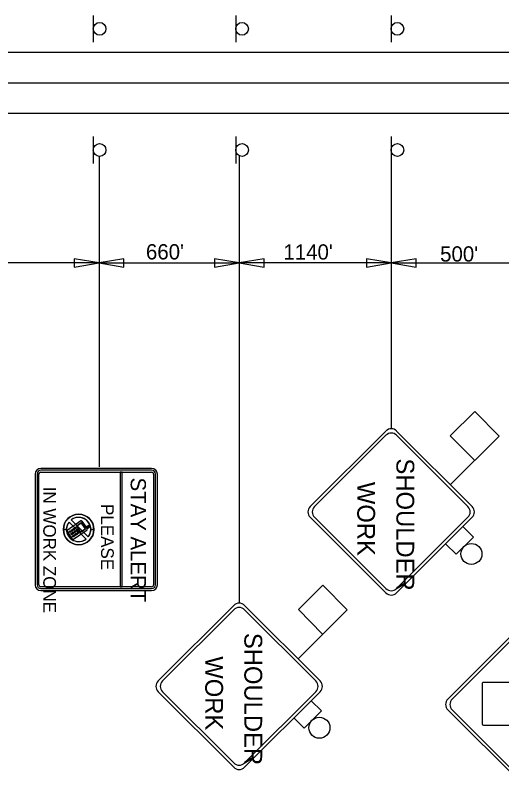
# Model space of a CAD drawing. Extents: x 2155255 to 2162649, y 140388 to 141878.
# Drawn here: x 2156772.7 to 2156963.6, y 140653 to 140956.6 of the extents above; entities that cross this region are included whole.
import ezdxf

# ---------------------------------------------------------------- set-up
doc = ezdxf.new("R2010")
doc.units = 0
for name, color, linetype in [('5', 7, 'Continuous'), ('Default', 7, 'Continuous'), ('PR_Dimensions1', 7, 'Continuous'), ('PR_Traffic_Control_Devices_Temp', 7, 'Continuous'), ('PR_Traffic_Temp_Txt', 7, 'Continuous'), ('TOPO_Asphalt', 7, 'Continuous')]:
    doc.layers.add(name, color=color, linetype=linetype)

# ---------------------------------------------------------------- blocks, each defined once
blk = doc.blocks.new('FLSHFLAG')
at = {"layer": 'Default'}
for p, q in [((-1.202, 14.125), (0.838, 16.147)), ((0.838, 16.147), (4.9, 12.085)), ((0.819, 12.085), (-1.202, 14.125)), ((0.819, 12.085), (2.86, 14.106)), ((9.258, 14.004), (8.403, 13.149)), ((9.258, 14.004), (10.685, 12.576)), ((10.685, 12.576), (9.831, 11.722))]:
    blk.add_line(p, q, dxfattribs=at)
blk.add_circle((10.653, 13.836), 0.873, dxfattribs=at)
blk = doc.blocks.new('TCSIGN')
at = {"layer": 'Default'}
blk.add_line((5.26, 2.5), (-5.26, 2.5), dxfattribs=at)
blk.add_circle((0, 0), 2.5, dxfattribs=at)
blk = doc.blocks.new('Arrowhd')
at = {"layer": 'Default'}
blk.add_lwpolyline([(0.3175, -0.0529), (0.3175, 0.0529), (0, 0)], close=True, dxfattribs=at)
blk = doc.blocks.new('W3-5_1')
at = {"layer": '5'}
for p, q in [((0.808, 7.633), (6.735, 13.56)), ((13.56, 7.633), (7.633, 13.56)), ((6.735, 0.808), (0.808, 6.735)), ((7.633, 0.808), (13.56, 6.735))]:
    blk.add_line(p, q, dxfattribs=at)
for centre, start, end in [((7.184, 13.111), 45, 135), ((1.257, 7.184), 135, 225), ((13.111, 7.184), 315, 45), ((7.184, 1.257), 225, 315)]:
    blk.add_arc(centre, 0.635, start, end, dxfattribs=at)
at = {"layer": 'Default'}
for p, q in [((0.448, 7.633), (6.735, 13.919)), ((13.919, 7.633), (7.633, 13.919)), ((6.95, 12.723), (4.277, 10.304)), ((9.984, 10.322), (7.366, 12.687)), ((5.352, 8.019), (5.352, 3.415)), ((8.797, 8.13), (5.464, 8.13)), ((8.908, 3.415), (8.908, 8.019)), ((6.735, 0.449), (0.448, 6.735)), ((7.633, 0.449), (13.919, 6.735)), ((5.464, 3.304), (8.797, 3.304))]:
    blk.add_line(p, q, dxfattribs=at)
for points in [[(4.277, 10.304), (6.95, 12.723)], [(7.366, 12.687), (9.984, 10.322)], [(4.584, 9.924), (6.553, 10.412), (6.553, 8.913), (7.745, 8.913), (7.745, 10.448), (9.677, 9.96)], [(9.677, 9.96), (7.745, 10.448), (7.745, 8.913), (6.553, 8.913), (6.553, 10.412), (4.584, 9.924)]]:
    blk.add_lwpolyline(points, dxfattribs=at)
for centre, radius, start, end in [((7.184, 13.47), 0.635, 45, 135), ((7.141, 12.512), 0.285, 37.91416, 132.14933), ((7.141, 12.512), 0.285, 37.91416, 132.14933), ((4.519, 10.186), 0.269, 154.09026, 283.9085), ((4.519, 10.186), 0.269, 154.09026, 283.9085), ((9.825, 10.146), 0.237, 231.34169, 47.91235), ((9.825, 10.146), 0.237, 231.34169, 47.91235), ((5.464, 8.019), 0.111, 90, 180), ((8.797, 8.019), 0.111, 0, 90), ((0.897, 7.184), 0.635, 135, 225), ((13.47, 7.184), 0.635, 315, 45), ((5.464, 3.415), 0.111, 180, 270), ((8.797, 3.415), 0.111, 270, 0), ((7.184, 0.898), 0.635, 225, 315)]:
    blk.add_arc(centre, radius, start, end, dxfattribs=at)
for s, p in [('SPEED', (5.649, 6.987)), ('LIMIT', (5.945, 5.929))]:
    blk.add_text(s, height=0.635, dxfattribs=at).set_placement(p)
blk = doc.blocks.new('CW21-5')
at = {"layer": '5'}
for p, q in [((0.318, 3.005), (2.651, 5.339)), ((5.338, 3.005), (3.005, 5.339)), ((2.651, 0.318), (0.318, 2.652)), ((3.005, 0.318), (5.338, 2.652))]:
    blk.add_line(p, q, dxfattribs=at)
for centre, start, end in [((2.828, 5.162), 45, 135), ((0.495, 2.828), 135, 225), ((5.162, 2.828), 315, 45), ((2.828, 0.495), 225, 315)]:
    blk.add_arc(centre, 0.25, start, end, dxfattribs=at)
at = {"layer": 'Default'}
for p, q in [((0.177, 3.005), (2.651, 5.48)), ((5.48, 3.005), (3.005, 5.48)), ((2.651, 0.177), (0.177, 2.652)), ((3.005, 0.177), (5.48, 2.652))]:
    blk.add_line(p, q, dxfattribs=at)
for centre, start, end in [((2.828, 5.303), 45, 135), ((0.353, 2.828), 135, 225), ((5.303, 2.828), 315, 45), ((2.828, 0.354), 225, 315)]:
    blk.add_arc(centre, 0.25, start, end, dxfattribs=at)
for s, p in [('SHOULDER', (1.076, 2.998)), ('WORK', (1.843, 1.717))]:
    blk.add_text(s, height=0.5833, dxfattribs=at).set_placement(p)

msp = doc.modelspace()

# ---------------------------------------------------------------- linework, layer by layer
at = {"layer": 'PR_Dimensions1'}
for p, q in [((2156805.54, 140901.15), (2156805.54, 140779.14)), ((2156860.58, 140901.56), (2156860.58, 140725.33)), ((2156920.31, 140901.63), (2156920.31, 140793.92)), ((2156805.54, 140859.25), (2156726.71, 140859.25)), ((2156805.54, 140859.25), (2156860.58, 140859.25)), ((2156920.31, 140859.25), (2156860.58, 140859.25)), ((2156920.31, 140859.25), (2156974.31, 140859.25))]:
    msp.add_line(p, q, dxfattribs=at)
at = {"layer": 'PR_Traffic_Control_Devices_Temp'}
for p, q in [((2156798.38, 140757.81), (2156793.01, 140754.05)), ((2156798.38, 140757.81), (2156793.01, 140754.05)), ((2156796.65, 140755.76), (2156798.55, 140757.09)), ((2156798.28, 140753.42), (2156796.65, 140755.76)), ((2156798.55, 140757.09), (2156800.18, 140754.75)), ((2156800.47, 140755.32), (2156798.81, 140757.69)), ((2156800.47, 140755.32), (2156798.81, 140757.69)), ((2156801.53, 140756.06), (2156800.47, 140755.32)), ((2156800.83, 140754.79), (2156800.47, 140755.32)), ((2156800.83, 140754.79), (2156800.47, 140755.32)), ((2156800.47, 140755.32), (2156800.83, 140754.79)), ((2156800.84, 140754.79), (2156801.9, 140755.53)), ((2156801.92, 140755.87), (2156801.85, 140755.97)), ((2156792.98, 140753.61), (2156795.01, 140750.71)), ((2156792.98, 140753.61), (2156795.01, 140750.71)), ((2156795.44, 140750.59), (2156800.8, 140754.35)), ((2156795.44, 140750.59), (2156800.8, 140754.35)), ((2156800.18, 140754.75), (2156798.28, 140753.42)), ((2156800.83, 140754.79), (2156800.83, 140754.79)), ((2156800.83, 140754.79), (2156800.84, 140754.79))]:
    msp.add_line(p, q, dxfattribs=at)
for points in [[(2156826.19, 140778.47), (2156814.19, 140778.47), (2156782.68, 140778.47)], [(2156826.19, 140777.72), (2156782.68, 140777.72)], [(2156782.68, 140776.97), (2156826.19, 140776.97)], [(2156780.43, 140776.22), (2156780.43, 140732.71)], [(2156781.18, 140776.22), (2156781.18, 140732.71)], [(2156781.18, 140776.22), (2156781.93, 140776.22)], [(2156781.93, 140732.71), (2156781.93, 140776.22), (2156781.18, 140776.22)], [(2156826.94, 140776.22), (2156826.94, 140732.71)], [(2156827.69, 140732.71), (2156827.69, 140776.22)], [(2156828.44, 140732.71), (2156828.44, 140776.22)], [(2156794.6, 140758.25), (2156801.29, 140751.56)], [(2156794.61, 140758.25), (2156801.29, 140751.56)], [(2156793.73, 140757.38), (2156800.42, 140750.69)], [(2156800.42, 140750.69), (2156793.74, 140757.38)], [(2156796.65, 140755.76), (2156798.55, 140757.09), (2156800.18, 140754.75), (2156798.28, 140753.42), (2156796.65, 140755.76)], [(2156801.92, 140755.87), (2156801.85, 140755.97)], [(2156791.51, 140754.47), (2156792.75, 140754.47)], [(2156792.75, 140754.47), (2156791.51, 140754.47)], [(2156792.98, 140753.61), (2156795.01, 140750.71)], [(2156803.51, 140754.47), (2156802.28, 140754.47)], [(2156802.28, 140754.47), (2156803.51, 140754.47)], [(2156826.19, 140731.96), (2156782.68, 140731.96)], [(2156782.68, 140731.21), (2156826.19, 140731.21)], [(2156782.68, 140730.46), (2156814.19, 140730.46), (2156826.19, 140730.46)]]:
    msp.add_lwpolyline(points, dxfattribs=at)
for points in [[(2156814.56, 140776.97), (2156813.81, 140776.97), (2156813.81, 140731.96), (2156814.56, 140731.96)], [(2156814.56, 140776.97), (2156813.81, 140776.97), (2156813.81, 140731.96), (2156814.56, 140731.96)], [(2156796.65, 140755.76), (2156798.28, 140753.42), (2156800.18, 140754.75), (2156798.55, 140757.09)], [(2156800.47, 140755.32), (2156801.53, 140756.06), (2156800.47, 140755.32), (2156800.84, 140754.79), (2156801.9, 140755.53), (2156800.84, 140754.79), (2156800.83, 140754.79), (2156800.83, 140754.79), (2156798.81, 140757.69), (2156798.81, 140757.69)]]:
    msp.add_lwpolyline(points, close=True, dxfattribs=at)
msp.add_circle((2156797.51, 140754.47), 6, dxfattribs=at)
msp.add_circle((2156797.51, 140754.47), 6, dxfattribs=at)
for centre, radius, start, end in [((2156782.68, 140776.22), 2.25, 90, 180), ((2156782.68, 140776.22), 1.5, 90, 180), ((2156782.68, 140776.22), 0.75, 90, 180), ((2156826.19, 140776.22), 2.25, 360, 90), ((2156826.19, 140776.22), 1.5, 360, 90), ((2156826.19, 140776.22), 0.75, 360, 90), ((2156797.51, 140754.47), 6, 0.0031, 179.9938), ((2156797.51, 140754.47), 4.77, 0.004, 127.5856), ((2156797.51, 140754.47), 4.77, 322.4137, 127.5863), ((2156797.51, 140754.47), 4.77, 322.4137, 127.5863), ((2156797.51, 140754.47), 4.77, 142.4137, 307.5863), ((2156797.51, 140754.47), 4.77, 142.4137, 307.5863), ((2156797.51, 140754.47), 4.77, 142.4117, 179.9933), ((2156797.51, 140754.47), 6, 179.9992, 359.9992), ((2156797.51, 140754.47), 4.77, 179.9991, 307.5866), ((2156797.51, 140754.47), 4.77, 322.4162, 0.0037), ((2156782.68, 140732.71), 2.25, 180, 270), ((2156782.68, 140732.71), 1.5, 180, 270), ((2156782.68, 140732.71), 0.75, 180, 270), ((2156826.19, 140732.71), 2.25, 270, 360), ((2156826.19, 140732.71), 1.5, 270, 360), ((2156826.19, 140732.71), 0.75, 270, 360)]:
    msp.add_arc(centre, radius, start, end, dxfattribs=at)
for centre, major_axis in [((2156796.19, 140755.02), (0.196, -0.28)), ((2156796.19, 140755.02), (0.196, -0.28)), ((2156796.19, 140755.02), (0.196, -0.28)), ((2156794.12, 140753.57), (0.196, -0.28)), ((2156794.12, 140753.57), (0.196, -0.28)), ((2156794.12, 140753.57), (0.196, -0.28)), ((2156794.74, 140752.68), (0.196, -0.28)), ((2156794.74, 140752.68), (0.196, -0.28)), ((2156794.74, 140752.68), (0.196, -0.28)), ((2156794.82, 140754.06), (0.196, -0.28)), ((2156794.82, 140754.06), (0.196, -0.28)), ((2156795.36, 140751.79), (-0.196, 0.28)), ((2156795.36, 140751.79), (-0.196, 0.28)), ((2156795.36, 140751.79), (-0.196, 0.28)), ((2156795.44, 140753.17), (0.196, -0.28)), ((2156795.44, 140753.17), (0.196, -0.28)), ((2156795.44, 140753.17), (0.196, -0.28)), ((2156795.51, 140754.55), (0.196, -0.28)), ((2156795.51, 140754.55), (0.196, -0.28)), ((2156795.51, 140754.55), (0.196, -0.28)), ((2156796.06, 140752.28), (-0.196, 0.28)), ((2156796.06, 140752.28), (-0.196, 0.28)), ((2156796.06, 140752.28), (-0.196, 0.28)), ((2156796.13, 140753.66), (0.196, -0.28)), ((2156796.13, 140753.66), (0.196, -0.28)), ((2156796.13, 140753.66), (0.196, -0.28)), ((2156796.75, 140752.77), (-0.196, 0.28)), ((2156796.75, 140752.77), (-0.196, 0.28)), ((2156796.75, 140752.77), (-0.196, 0.28)), ((2156796.81, 140754.13), (0.196, -0.28)), ((2156796.81, 140754.13), (0.196, -0.28)), ((2156796.81, 140754.13), (0.196, -0.28)), ((2156797.44, 140753.25), (-0.196, 0.28)), ((2156797.44, 140753.25), (-0.196, 0.28)), ((2156797.44, 140753.25), (-0.196, 0.28))]:
    msp.add_ellipse(centre, major_axis=major_axis, ratio=0.8, dxfattribs=at)
for centre, major_axis, start_param, end_param in [((2156798.58, 140757.53), (-0.2, 0.285), 4.712389, 6.283185), ((2156798.58, 140757.53), (-0.2, 0.285), 4.712389, 6.283185), ((2156798.58, 140757.53), (-0.2, 0.285), 4.712389, 6.283185), ((2156798.58, 140757.53), (-0.2, 0.285), 4.712389, 6.283185), ((2156801.68, 140755.85), (-0.15, 0.214), 4.712389, 6.283185), ((2156801.68, 140755.85), (-0.15, 0.214), 4.712389, 6.283185), ((2156801.68, 140755.85), (-0.15, 0.214), 4.712389, 6.283185), ((2156801.75, 140755.75), (0.15, -0.214), 0, 1.570796), ((2156801.75, 140755.75), (-0.15, 0.214), 3.141593, 4.712389), ((2156801.75, 140755.75), (0.15, -0.214), 0, 1.570796), ((2156793.21, 140753.77), (-0.2, 0.285), 0, 1.570796), ((2156793.21, 140753.77), (-0.2, 0.285), 0, 1.570796), ((2156793.21, 140753.77), (-0.2, 0.285), 6.283185, 7.853982), ((2156800.6, 140754.63), (0.2, -0.285), 0, 1.570796), ((2156800.6, 140754.63), (-0.2, 0.285), 3.141593, 4.712389), ((2156800.6, 140754.63), (-0.2, 0.285), 3.141593, 4.712389), ((2156800.6, 140754.63), (0.2, -0.285), 0, 1.570795), ((2156795.24, 140750.87), (0.2, -0.285), 4.712389, 6.283185), ((2156795.24, 140750.87), (0.2, -0.285), 4.712389, 6.283185), ((2156795.24, 140750.87), (0.2, -0.285), 4.712389, 6.283185)]:
    msp.add_ellipse(centre, major_axis=major_axis, ratio=0.8, start_param=start_param, end_param=end_param, dxfattribs=at)
at = {"layer": 'TOPO_Asphalt'}
for p, q in [((2157147.83, 140941.97), (2156447.24, 140941.97)), ((2157147.76, 140929.97), (2156447.37, 140929.97)), ((2157147.69, 140917.97), (2156447.51, 140917.97)), ((2157147.69, 140917.97), (2156447.51, 140917.97))]:
    msp.add_line(p, q, dxfattribs=at)

# ---------------------------------------------------------------- block references
at = {"layer": 'PR_Dimensions1', "xscale": 30.761459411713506, "yscale": 30.761459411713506, "rotation": 180}
for p in [(2156805.54, 140859.25), (2156860.58, 140859.25), (2156920.31, 140859.25)]:
    msp.add_blockref('Arrowhd', p, dxfattribs=at)
at = {"layer": 'PR_Dimensions1', "xscale": 30.761459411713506, "yscale": 30.761459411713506}
for p in [(2156805.54, 140859.25), (2156860.58, 140859.25), (2156920.31, 140859.25)]:
    msp.add_blockref('Arrowhd', p, dxfattribs=at)
at = {"layer": 'PR_Traffic_Control_Devices_Temp', "rotation": 89.99999999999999}
for p in [(2156805.74, 140951.31), (2156861.71, 140951.31), (2156922.73, 140951.31), (2156805.74, 140903.66), (2156861.71, 140903.66), (2156922.73, 140903.66)]:
    msp.add_blockref('TCSIGN', p, dxfattribs=at)
at = {"layer": 'PR_Traffic_Control_Devices_Temp', "rotation": -90.00000000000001}
for name, p, xscale, yscale in [('FLSHFLAG', (2156886.4, 140795.17), 4.7244, 4.7244), ('CW21-5', (2156886.34, 140795.3), 12, 12), ('FLSHFLAG', (2156826.71, 140726.84), 4.7244, 4.7244), ('CW21-5', (2156826.62, 140726.72), 12, 12), ('W3-5_1', (2156940.39, 140719.56), 4.72, 4.72)]:
    msp.add_blockref(name, p, dxfattribs=dict(at, xscale=xscale, yscale=yscale))

# ---------------------------------------------------------------- texts
at = {"layer": 'PR_Traffic_Control_Devices_Temp'}
for s, height, p in [('STAY ALERT', 6, (2156817.94, 140774.88)), ('IN WORK ZONE', 4.9872, (2156783.62, 140771.28)), ('PLEASE', 4.987, (2156806.3, 140764.44))]:
    msp.add_text(s, height=height, rotation=270, dxfattribs=at).set_placement(p)
at = {"layer": 'PR_Traffic_Temp_Txt'}
for s, p in [("660'", (2156823.95, 140860.64)), ("1140'", (2156877.94, 140860.58)), ("500'", (2156939.49, 140859.8))]:
    msp.add_text(s, height=6, rotation=360, dxfattribs=at).set_placement(p)

doc.saveas('drawing.dxf')
